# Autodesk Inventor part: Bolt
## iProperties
Shininess: 77.0
Length Units: 11269
Angle Units: 11279
Time Units: 11290
Mass Units: 11283
Length Display Precision: 3
Angle Display Precision: 2
Created: 2002-02
Part Number: Bolt
Document SubType Name: Modeling
Designer: ***
Density: 1 g/cm^3
Density: 0.0
Volumn: 0.0
Area: 0.0
PropertySet Name: Model Information
Control State: 0
Master: False
Checked Out: False
Author: ***
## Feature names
1. Extrusion1
2. Fillet1
3. Extrusion2
4. Extrusion3
